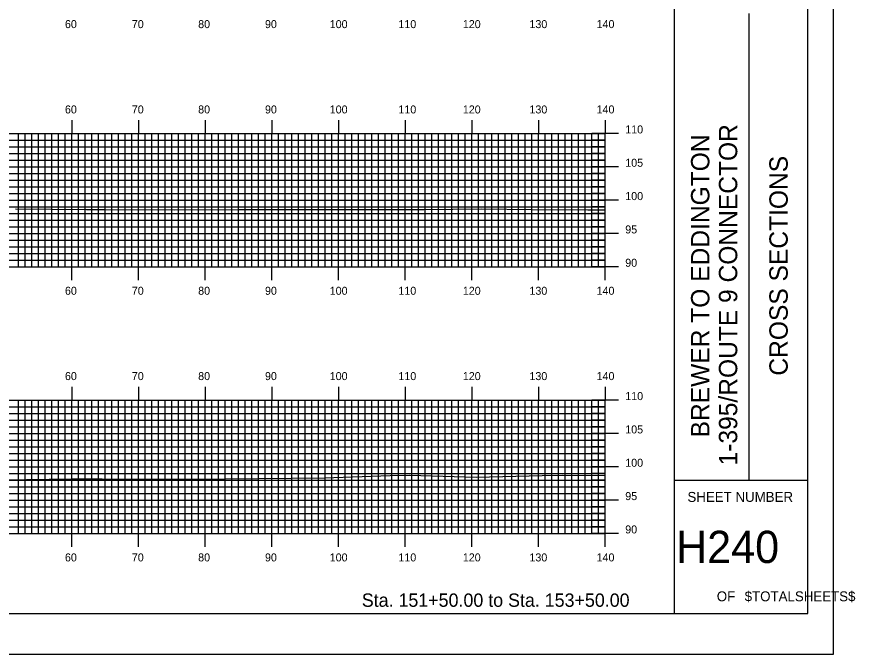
# Model space of a CAD drawing. Extents: x 1778712 to 1779055, y 442591 to 442811.
# Drawn here: x 1778929.6 to 1779055.3, y 442590.5 to 442686.2 of the extents above; entities that cross this region are included whole.
import ezdxf

# ---------------------------------------------------------------- set-up
doc = ezdxf.new("R2010")
doc.units = 0
for name, color, linetype in [('BORDER', 7, 'Continuous'), ('H_V ANNOTATION', 7, 'Continuous'), ('MAJOR', 7, 'Continuous'), ('MINOR', 7, 'Continuous'), ('PLOT BOUNDARY', 7, 'Continuous'), ('S_Roadway_Centerline', 7, 'Continuous')]:
    doc.layers.add(name, color=color, linetype=linetype)

msp = doc.modelspace()

# ---------------------------------------------------------------- linework, layer by layer
at = {"layer": 'BORDER'}
for p, q in [((1779028.22, 442596.67), (1779028.22, 442806.67)), ((1779039.4, 442616.67), (1779039.4, 442686.67)), ((1779028.22, 442616.67), (1779048.22, 442616.67))]:
    msp.add_line(p, q, dxfattribs=at)
msp.add_lwpolyline([(1778728.22, 442596.67), (1779048.22, 442596.67), (1779048.22, 442806.67), (1778728.22, 442806.67)], close=True, dxfattribs=at)
at = {"layer": 'MAJOR'}
for p, q in [((1778937.82, 442670.67), (1778937.82, 442668.67)), ((1778947.82, 442670.67), (1778947.82, 442668.67)), ((1778957.82, 442670.67), (1778957.82, 442668.67)), ((1778967.82, 442670.67), (1778967.82, 442668.67)), ((1778977.82, 442670.67), (1778977.82, 442668.67)), ((1778987.82, 442670.67), (1778987.82, 442668.67)), ((1778997.82, 442670.67), (1778997.82, 442668.67)), ((1779007.82, 442670.67), (1779007.82, 442668.67)), ((1779017.82, 442670.67), (1779017.82, 442668.67)), ((1778737.82, 442668.67), (1779017.82, 442668.67)), ((1778737.82, 442668.67), (1779017.82, 442668.67)), ((1778937.82, 442648.67), (1778937.82, 442668.67)), ((1778947.82, 442648.67), (1778947.82, 442668.67)), ((1778957.82, 442648.67), (1778957.82, 442668.67)), ((1778967.82, 442648.67), (1778967.82, 442668.67)), ((1778977.82, 442648.67), (1778977.82, 442668.67)), ((1778987.82, 442648.67), (1778987.82, 442668.67)), ((1778997.82, 442648.67), (1778997.82, 442668.67)), ((1779007.82, 442648.67), (1779007.82, 442668.67)), ((1779019.82, 442668.67), (1779015.81, 442668.67)), ((1779017.82, 442648.67), (1779017.82, 442668.67)), ((1779017.82, 442648.67), (1779017.82, 442668.67)), ((1778737.82, 442663.67), (1779017.82, 442663.67)), ((1779019.82, 442663.67), (1779015.81, 442663.67)), ((1778737.82, 442658.67), (1779017.82, 442658.67)), ((1779019.82, 442658.67), (1779015.81, 442658.67)), ((1778737.82, 442653.67), (1779017.82, 442653.67)), ((1779019.82, 442653.67), (1779015.81, 442653.67)), ((1778737.82, 442648.67), (1779017.82, 442648.67)), ((1778737.82, 442648.67), (1779017.82, 442648.67)), ((1778937.82, 442646.66), (1778937.82, 442648.67)), ((1778947.82, 442646.66), (1778947.82, 442648.67)), ((1778957.82, 442646.66), (1778957.82, 442648.67)), ((1778967.82, 442646.66), (1778967.82, 442648.67)), ((1778977.82, 442646.66), (1778977.82, 442648.67)), ((1778987.82, 442646.66), (1778987.82, 442648.67)), ((1778997.82, 442646.66), (1778997.82, 442648.67)), ((1779007.82, 442646.66), (1779007.82, 442648.67)), ((1779019.82, 442648.67), (1779015.81, 442648.67)), ((1779017.82, 442646.66), (1779017.82, 442648.67)), ((1778937.82, 442630.67), (1778937.82, 442628.67)), ((1778947.82, 442630.67), (1778947.82, 442628.67)), ((1778957.82, 442630.67), (1778957.82, 442628.67)), ((1778967.82, 442630.67), (1778967.82, 442628.67)), ((1778977.82, 442630.67), (1778977.82, 442628.67)), ((1778987.82, 442630.67), (1778987.82, 442628.67)), ((1778997.82, 442630.67), (1778997.82, 442628.67)), ((1779007.82, 442630.67), (1779007.82, 442628.67)), ((1779017.82, 442630.67), (1779017.82, 442628.67)), ((1778737.82, 442628.67), (1779017.82, 442628.67)), ((1778737.82, 442628.67), (1779017.82, 442628.67)), ((1778937.82, 442608.67), (1778937.82, 442628.67)), ((1778947.82, 442608.67), (1778947.82, 442628.67)), ((1778957.82, 442608.67), (1778957.82, 442628.67)), ((1778967.82, 442608.67), (1778967.82, 442628.67)), ((1778977.82, 442608.67), (1778977.82, 442628.67)), ((1778987.82, 442608.67), (1778987.82, 442628.67)), ((1778997.82, 442608.67), (1778997.82, 442628.67)), ((1779007.82, 442608.67), (1779007.82, 442628.67)), ((1779019.82, 442628.67), (1779015.81, 442628.67)), ((1779017.82, 442608.67), (1779017.82, 442628.67)), ((1779017.82, 442608.67), (1779017.82, 442628.67)), ((1778737.82, 442623.67), (1779017.82, 442623.67)), ((1779019.82, 442623.67), (1779015.81, 442623.67)), ((1778737.82, 442618.67), (1779017.82, 442618.67)), ((1779019.82, 442618.67), (1779015.81, 442618.67)), ((1778737.82, 442613.67), (1779017.82, 442613.67)), ((1779019.82, 442613.67), (1779015.81, 442613.67)), ((1778737.82, 442608.67), (1779017.82, 442608.67)), ((1778737.82, 442608.67), (1779017.82, 442608.67)), ((1778937.82, 442606.66), (1778937.82, 442608.67)), ((1778947.82, 442606.66), (1778947.82, 442608.67)), ((1778957.82, 442606.66), (1778957.82, 442608.67)), ((1778967.82, 442606.66), (1778967.82, 442608.67)), ((1778977.82, 442606.66), (1778977.82, 442608.67)), ((1778987.82, 442606.66), (1778987.82, 442608.67)), ((1778997.82, 442606.66), (1778997.82, 442608.67)), ((1779007.82, 442606.66), (1779007.82, 442608.67)), ((1779019.82, 442608.67), (1779015.81, 442608.67)), ((1779017.82, 442606.66), (1779017.82, 442608.67))]:
    msp.add_line(p, q, dxfattribs=at)
at = {"layer": 'MINOR'}
for p, q in [((1778929.82, 442648.67), (1778929.82, 442668.67)), ((1778930.82, 442648.67), (1778930.82, 442668.67)), ((1778931.82, 442648.67), (1778931.82, 442668.67)), ((1778932.82, 442648.67), (1778932.82, 442668.67)), ((1778933.82, 442648.67), (1778933.82, 442668.67)), ((1778934.82, 442648.67), (1778934.82, 442668.67)), ((1778935.82, 442648.67), (1778935.82, 442668.67)), ((1778936.82, 442648.67), (1778936.82, 442668.67)), ((1778938.82, 442648.67), (1778938.82, 442668.67)), ((1778939.82, 442648.67), (1778939.82, 442668.67)), ((1778940.82, 442648.67), (1778940.82, 442668.67)), ((1778941.82, 442648.67), (1778941.82, 442668.67)), ((1778942.82, 442648.67), (1778942.82, 442668.67)), ((1778943.82, 442648.67), (1778943.82, 442668.67)), ((1778944.82, 442648.67), (1778944.82, 442668.67)), ((1778945.82, 442648.67), (1778945.82, 442668.67)), ((1778946.82, 442648.67), (1778946.82, 442668.67)), ((1778948.82, 442648.67), (1778948.82, 442668.67)), ((1778949.82, 442648.67), (1778949.82, 442668.67)), ((1778950.82, 442648.67), (1778950.82, 442668.67)), ((1778951.82, 442648.67), (1778951.82, 442668.67)), ((1778952.82, 442648.67), (1778952.82, 442668.67)), ((1778953.82, 442648.67), (1778953.82, 442668.67)), ((1778954.82, 442648.67), (1778954.82, 442668.67)), ((1778955.82, 442648.67), (1778955.82, 442668.67)), ((1778956.82, 442648.67), (1778956.82, 442668.67)), ((1778958.82, 442648.67), (1778958.82, 442668.67)), ((1778959.82, 442648.67), (1778959.82, 442668.67)), ((1778960.82, 442648.67), (1778960.82, 442668.67)), ((1778961.82, 442648.67), (1778961.82, 442668.67)), ((1778962.82, 442648.67), (1778962.82, 442668.67)), ((1778963.82, 442648.67), (1778963.82, 442668.67)), ((1778964.82, 442648.67), (1778964.82, 442668.67)), ((1778965.82, 442648.67), (1778965.82, 442668.67)), ((1778966.82, 442648.67), (1778966.82, 442668.67)), ((1778968.82, 442648.67), (1778968.82, 442668.67)), ((1778969.82, 442648.67), (1778969.82, 442668.67)), ((1778970.82, 442648.67), (1778970.82, 442668.67)), ((1778971.82, 442648.67), (1778971.82, 442668.67)), ((1778972.82, 442648.67), (1778972.82, 442668.67)), ((1778973.82, 442648.67), (1778973.82, 442668.67)), ((1778974.82, 442648.67), (1778974.82, 442668.67)), ((1778975.82, 442648.67), (1778975.82, 442668.67)), ((1778976.82, 442648.67), (1778976.82, 442668.67)), ((1778978.82, 442648.67), (1778978.82, 442668.67)), ((1778979.82, 442648.67), (1778979.82, 442668.67)), ((1778980.82, 442648.67), (1778980.82, 442668.67)), ((1778981.82, 442648.67), (1778981.82, 442668.67)), ((1778982.82, 442648.67), (1778982.82, 442668.67)), ((1778983.82, 442648.67), (1778983.82, 442668.67)), ((1778984.82, 442648.67), (1778984.82, 442668.67)), ((1778985.82, 442648.67), (1778985.82, 442668.67)), ((1778986.82, 442648.67), (1778986.82, 442668.67)), ((1778988.82, 442648.67), (1778988.82, 442668.67)), ((1778989.82, 442648.67), (1778989.82, 442668.67)), ((1778990.82, 442648.67), (1778990.82, 442668.67)), ((1778991.82, 442648.67), (1778991.82, 442668.67)), ((1778992.82, 442648.67), (1778992.82, 442668.67)), ((1778993.82, 442648.67), (1778993.82, 442668.67)), ((1778994.82, 442648.67), (1778994.82, 442668.67)), ((1778995.82, 442648.67), (1778995.82, 442668.67)), ((1778996.82, 442648.67), (1778996.82, 442668.67)), ((1778998.82, 442648.67), (1778998.82, 442668.67)), ((1778999.82, 442648.67), (1778999.82, 442668.67)), ((1779000.82, 442648.67), (1779000.82, 442668.67)), ((1779001.82, 442648.67), (1779001.82, 442668.67)), ((1779002.82, 442648.67), (1779002.82, 442668.67)), ((1779003.82, 442648.67), (1779003.82, 442668.67)), ((1779004.82, 442648.67), (1779004.82, 442668.67)), ((1779005.82, 442648.67), (1779005.82, 442668.67)), ((1779006.82, 442648.67), (1779006.82, 442668.67)), ((1779008.82, 442648.67), (1779008.82, 442668.67)), ((1779009.82, 442648.67), (1779009.82, 442668.67)), ((1779010.82, 442648.67), (1779010.82, 442668.67)), ((1779011.82, 442648.67), (1779011.82, 442668.67)), ((1779012.82, 442648.67), (1779012.82, 442668.67)), ((1779013.82, 442648.67), (1779013.82, 442668.67)), ((1779014.82, 442648.67), (1779014.82, 442668.67)), ((1779015.82, 442648.67), (1779015.82, 442668.67)), ((1779016.82, 442648.67), (1779016.82, 442668.67)), ((1778737.82, 442667.67), (1779017.82, 442667.67)), ((1779017.82, 442667.67), (1779015.81, 442667.67)), ((1778737.82, 442666.67), (1779017.82, 442666.67)), ((1779017.82, 442666.67), (1779015.81, 442666.67)), ((1778737.82, 442665.67), (1779017.82, 442665.67)), ((1778737.82, 442664.67), (1779017.82, 442664.67)), ((1779017.82, 442665.67), (1779015.81, 442665.67)), ((1779017.82, 442664.67), (1779015.81, 442664.67)), ((1778737.82, 442662.67), (1779017.82, 442662.67)), ((1779017.82, 442662.67), (1779015.81, 442662.67)), ((1778737.82, 442661.67), (1779017.82, 442661.67)), ((1779017.82, 442661.67), (1779015.81, 442661.67)), ((1778737.82, 442660.67), (1779017.82, 442660.67)), ((1778737.82, 442659.67), (1779017.82, 442659.67)), ((1779017.82, 442660.67), (1779015.81, 442660.67)), ((1779017.82, 442659.67), (1779015.81, 442659.67)), ((1778737.82, 442657.67), (1779017.82, 442657.67)), ((1779017.82, 442657.67), (1779015.81, 442657.67)), ((1778737.82, 442656.67), (1779017.82, 442656.67)), ((1779017.82, 442656.67), (1779015.81, 442656.67)), ((1778737.82, 442655.67), (1779017.82, 442655.67)), ((1778737.82, 442654.67), (1779017.82, 442654.67)), ((1779017.82, 442655.67), (1779015.81, 442655.67)), ((1779017.82, 442654.67), (1779015.81, 442654.67)), ((1778737.82, 442652.67), (1779017.82, 442652.67)), ((1779017.82, 442652.67), (1779015.81, 442652.67)), ((1778737.82, 442651.67), (1779017.82, 442651.67)), ((1779017.82, 442651.67), (1779015.81, 442651.67)), ((1778737.82, 442650.67), (1779017.82, 442650.67)), ((1778737.82, 442649.67), (1779017.82, 442649.67)), ((1779017.82, 442650.67), (1779015.81, 442650.67)), ((1779017.82, 442649.67), (1779015.81, 442649.67)), ((1778929.82, 442608.67), (1778929.82, 442628.67)), ((1778930.82, 442608.67), (1778930.82, 442628.67)), ((1778931.82, 442608.67), (1778931.82, 442628.67)), ((1778932.82, 442608.67), (1778932.82, 442628.67)), ((1778933.82, 442608.67), (1778933.82, 442628.67)), ((1778934.82, 442608.67), (1778934.82, 442628.67)), ((1778935.82, 442608.67), (1778935.82, 442628.67)), ((1778936.82, 442608.67), (1778936.82, 442628.67)), ((1778938.82, 442608.67), (1778938.82, 442628.67)), ((1778939.82, 442608.67), (1778939.82, 442628.67)), ((1778940.82, 442608.67), (1778940.82, 442628.67)), ((1778941.82, 442608.67), (1778941.82, 442628.67)), ((1778942.82, 442608.67), (1778942.82, 442628.67)), ((1778943.82, 442608.67), (1778943.82, 442628.67)), ((1778944.82, 442608.67), (1778944.82, 442628.67)), ((1778945.82, 442608.67), (1778945.82, 442628.67)), ((1778946.82, 442608.67), (1778946.82, 442628.67)), ((1778948.82, 442608.67), (1778948.82, 442628.67)), ((1778949.82, 442608.67), (1778949.82, 442628.67)), ((1778950.82, 442608.67), (1778950.82, 442628.67)), ((1778951.82, 442608.67), (1778951.82, 442628.67)), ((1778952.82, 442608.67), (1778952.82, 442628.67)), ((1778953.82, 442608.67), (1778953.82, 442628.67)), ((1778954.82, 442608.67), (1778954.82, 442628.67)), ((1778955.82, 442608.67), (1778955.82, 442628.67)), ((1778956.82, 442608.67), (1778956.82, 442628.67)), ((1778958.82, 442608.67), (1778958.82, 442628.67)), ((1778959.82, 442608.67), (1778959.82, 442628.67)), ((1778960.82, 442608.67), (1778960.82, 442628.67)), ((1778961.82, 442608.67), (1778961.82, 442628.67)), ((1778962.82, 442608.67), (1778962.82, 442628.67)), ((1778963.82, 442608.67), (1778963.82, 442628.67)), ((1778964.82, 442608.67), (1778964.82, 442628.67)), ((1778965.82, 442608.67), (1778965.82, 442628.67)), ((1778966.82, 442608.67), (1778966.82, 442628.67)), ((1778968.82, 442608.67), (1778968.82, 442628.67)), ((1778969.82, 442608.67), (1778969.82, 442628.67)), ((1778970.82, 442608.67), (1778970.82, 442628.67)), ((1778971.82, 442608.67), (1778971.82, 442628.67)), ((1778972.82, 442608.67), (1778972.82, 442628.67)), ((1778973.82, 442608.67), (1778973.82, 442628.67)), ((1778974.82, 442608.67), (1778974.82, 442628.67)), ((1778975.82, 442608.67), (1778975.82, 442628.67)), ((1778976.82, 442608.67), (1778976.82, 442628.67)), ((1778978.82, 442608.67), (1778978.82, 442628.67)), ((1778979.82, 442608.67), (1778979.82, 442628.67)), ((1778980.82, 442608.67), (1778980.82, 442628.67)), ((1778981.82, 442608.67), (1778981.82, 442628.67)), ((1778982.82, 442608.67), (1778982.82, 442628.67)), ((1778983.82, 442608.67), (1778983.82, 442628.67)), ((1778984.82, 442608.67), (1778984.82, 442628.67)), ((1778985.82, 442608.67), (1778985.82, 442628.67)), ((1778986.82, 442608.67), (1778986.82, 442628.67)), ((1778988.82, 442608.67), (1778988.82, 442628.67)), ((1778989.82, 442608.67), (1778989.82, 442628.67)), ((1778990.82, 442608.67), (1778990.82, 442628.67)), ((1778991.82, 442608.67), (1778991.82, 442628.67)), ((1778992.82, 442608.67), (1778992.82, 442628.67)), ((1778993.82, 442608.67), (1778993.82, 442628.67)), ((1778994.82, 442608.67), (1778994.82, 442628.67)), ((1778995.82, 442608.67), (1778995.82, 442628.67)), ((1778996.82, 442608.67), (1778996.82, 442628.67)), ((1778998.82, 442608.67), (1778998.82, 442628.67)), ((1778999.82, 442608.67), (1778999.82, 442628.67)), ((1779000.82, 442608.67), (1779000.82, 442628.67)), ((1779001.82, 442608.67), (1779001.82, 442628.67)), ((1779002.82, 442608.67), (1779002.82, 442628.67)), ((1779003.82, 442608.67), (1779003.82, 442628.67)), ((1779004.82, 442608.67), (1779004.82, 442628.67)), ((1779005.82, 442608.67), (1779005.82, 442628.67)), ((1779006.82, 442608.67), (1779006.82, 442628.67)), ((1779008.82, 442608.67), (1779008.82, 442628.67)), ((1779009.82, 442608.67), (1779009.82, 442628.67)), ((1779010.82, 442608.67), (1779010.82, 442628.67)), ((1779011.82, 442608.67), (1779011.82, 442628.67)), ((1779012.82, 442608.67), (1779012.82, 442628.67)), ((1779013.82, 442608.67), (1779013.82, 442628.67)), ((1779014.82, 442608.67), (1779014.82, 442628.67)), ((1779015.82, 442608.67), (1779015.82, 442628.67)), ((1779016.82, 442608.67), (1779016.82, 442628.67)), ((1778737.82, 442627.67), (1779017.82, 442627.67)), ((1779017.82, 442627.67), (1779015.81, 442627.67)), ((1778737.82, 442626.67), (1779017.82, 442626.67)), ((1778737.82, 442625.67), (1779017.82, 442625.67)), ((1779017.82, 442626.67), (1779015.81, 442626.67)), ((1779017.82, 442625.67), (1779015.81, 442625.67)), ((1778737.82, 442624.67), (1779017.82, 442624.67)), ((1779017.82, 442624.67), (1779015.81, 442624.67)), ((1778737.82, 442622.67), (1779017.82, 442622.67)), ((1779017.82, 442622.67), (1779015.81, 442622.67)), ((1778737.82, 442621.67), (1779017.82, 442621.67)), ((1778737.82, 442620.67), (1779017.82, 442620.67)), ((1779017.82, 442621.67), (1779015.81, 442621.67)), ((1779017.82, 442620.67), (1779015.81, 442620.67)), ((1778737.82, 442619.67), (1779017.82, 442619.67)), ((1779017.82, 442619.67), (1779015.81, 442619.67)), ((1778737.82, 442617.67), (1779017.82, 442617.67)), ((1779017.82, 442617.67), (1779015.81, 442617.67)), ((1778737.82, 442616.67), (1779017.82, 442616.67)), ((1778737.82, 442615.67), (1779017.82, 442615.67)), ((1779017.82, 442616.67), (1779015.81, 442616.67)), ((1779017.82, 442615.67), (1779015.81, 442615.67)), ((1778737.82, 442614.67), (1779017.82, 442614.67)), ((1779017.82, 442614.67), (1779015.81, 442614.67)), ((1778737.82, 442612.67), (1779017.82, 442612.67)), ((1779017.82, 442612.67), (1779015.81, 442612.67)), ((1778737.82, 442611.67), (1779017.82, 442611.67)), ((1778737.82, 442610.67), (1779017.82, 442610.67)), ((1779017.82, 442611.67), (1779015.81, 442611.67)), ((1779017.82, 442610.67), (1779015.81, 442610.67)), ((1778737.82, 442609.67), (1779017.82, 442609.67)), ((1779017.82, 442609.67), (1779015.81, 442609.67))]:
    msp.add_line(p, q, dxfattribs=at)
at = {"layer": 'PLOT BOUNDARY'}
msp.add_lwpolyline([(1778712.03, 442590.55), (1779052.03, 442590.55), (1779052.03, 442810.55), (1778712.03, 442810.55)], close=True, dxfattribs=at)
at = {"layer": 'S_Roadway_Centerline'}
for points in [[(1778929.36, 442657.36), (1778940.03, 442657.27), (1778941.35, 442657.25), (1778942.85, 442657.24), (1778953.27, 442657.23), (1778962.84, 442657.24), (1778964.61, 442657.26), (1778966.54, 442657.24), (1778985.13, 442657.24), (1778990.59, 442657.26), (1778999.31, 442657.35), (1779006.84, 442657.28), (1779015.2, 442657.2), (1779017.82, 442657.22)], [(1778920.68, 442616.59), (1778937.87, 442616.84), (1778940.14, 442616.87), (1778942.37, 442616.85), (1778952.23, 442616.79), (1778960.82, 442616.85), (1778965.83, 442616.93), (1778975.72, 442616.99), (1778985.58, 442617.37), (1778988.49, 442617.39), (1778998.49, 442617.09), (1779008.38, 442617.36), (1779011.39, 442617.39), (1779017.82, 442617.35)]]:
    msp.add_lwpolyline(points, dxfattribs=at)

# ---------------------------------------------------------------- texts
at = {"layer": 'BORDER'}
for s, p in [('1-395/ROUTE 9 CONNECTOR', (1779037.62, 442618.87)), ('BREWER TO EDDINGTON', (1779033.44, 442623.07)), ('CROSS SECTIONS', (1779045.19, 442632.34))]:
    msp.add_text(s, height=2.7557, rotation=90, dxfattribs=at).set_placement(p)
for s, height, p in [('SHEET NUMBER', 1.4905, (1779030.15, 442613.4)), ('H240', 4.839, (1779028.43, 442604.23)), ('OF', 1.491, (1779034.55, 442598.49)), ('$TOTALSHEETS$', 1.4905, (1779038.73, 442598.49))]:
    msp.add_text(s, height=height, dxfattribs=at).set_placement(p)
at = {"layer": 'H_V ANNOTATION'}
for s, height, p in [('60', 1.2, (1778936.79, 442684.47)), ('70', 1.2, (1778946.82, 442684.47)), ('80', 1.2, (1778956.77, 442684.47)), ('90', 1.2, (1778966.79, 442684.47)), ('100', 1.2, (1778976.5, 442684.47)), ('110', 1.2, (1778986.8, 442684.47)), ('120', 1.2, (1778996.46, 442684.47)), ('130', 1.2, (1779006.45, 442684.47)), ('140', 1.2, (1779016.52, 442684.47)), ('60', 1.2, (1778936.79, 442671.67)), ('70', 1.2, (1778946.82, 442671.67)), ('80', 1.2, (1778956.77, 442671.67)), ('90', 1.2, (1778966.79, 442671.67)), ('100', 1.2, (1778976.5, 442671.67)), ('110', 1.2, (1778986.8, 442671.67)), ('120', 1.2, (1778996.46, 442671.67)), ('130', 1.2, (1779006.45, 442671.67)), ('140', 1.2, (1779016.52, 442671.67)), ('110', 1.2, (1779020.82, 442668.67)), ('105', 1.2, (1779020.82, 442663.67)), ('100', 1.2, (1779020.82, 442658.67)), ('95', 1.2, (1779020.82, 442653.67)), ('90', 1.2, (1779020.82, 442648.67)), ('60', 1.2, (1778936.79, 442644.47)), ('70', 1.2, (1778946.82, 442644.47)), ('80', 1.2, (1778956.77, 442644.47)), ('90', 1.2, (1778966.79, 442644.47)), ('100', 1.2, (1778976.5, 442644.47)), ('110', 1.2, (1778986.8, 442644.47)), ('120', 1.2, (1778996.46, 442644.47)), ('130', 1.2, (1779006.45, 442644.47)), ('140', 1.2, (1779016.52, 442644.47)), ('60', 1.2, (1778936.79, 442631.67)), ('70', 1.2, (1778946.82, 442631.67)), ('80', 1.2, (1778956.77, 442631.67)), ('90', 1.2, (1778966.79, 442631.67)), ('100', 1.2, (1778976.5, 442631.67)), ('110', 1.2, (1778986.8, 442631.67)), ('120', 1.2, (1778996.46, 442631.67)), ('130', 1.2, (1779006.45, 442631.67)), ('140', 1.2, (1779016.52, 442631.67)), ('110', 1.2, (1779020.82, 442628.67)), ('105', 1.2, (1779020.82, 442623.67)), ('100', 1.2, (1779020.82, 442618.67)), ('95', 1.2, (1779020.82, 442613.67)), ('90', 1.2, (1779020.82, 442608.67)), ('60', 1.2, (1778936.79, 442604.47)), ('70', 1.2, (1778946.82, 442604.47)), ('80', 1.2, (1778956.77, 442604.47)), ('90', 1.2, (1778966.79, 442604.47)), ('100', 1.2, (1778976.5, 442604.47)), ('110', 1.2, (1778986.8, 442604.47)), ('120', 1.2, (1778996.46, 442604.47)), ('130', 1.2, (1779006.45, 442604.47)), ('140', 1.2, (1779016.52, 442604.47)), ('Sta. 151+50.00 to Sta. 153+50.00', 2.0004, (1778981.31, 442597.66))]:
    msp.add_text(s, height=height, dxfattribs=at).set_placement(p)

doc.saveas('drawing.dxf')
